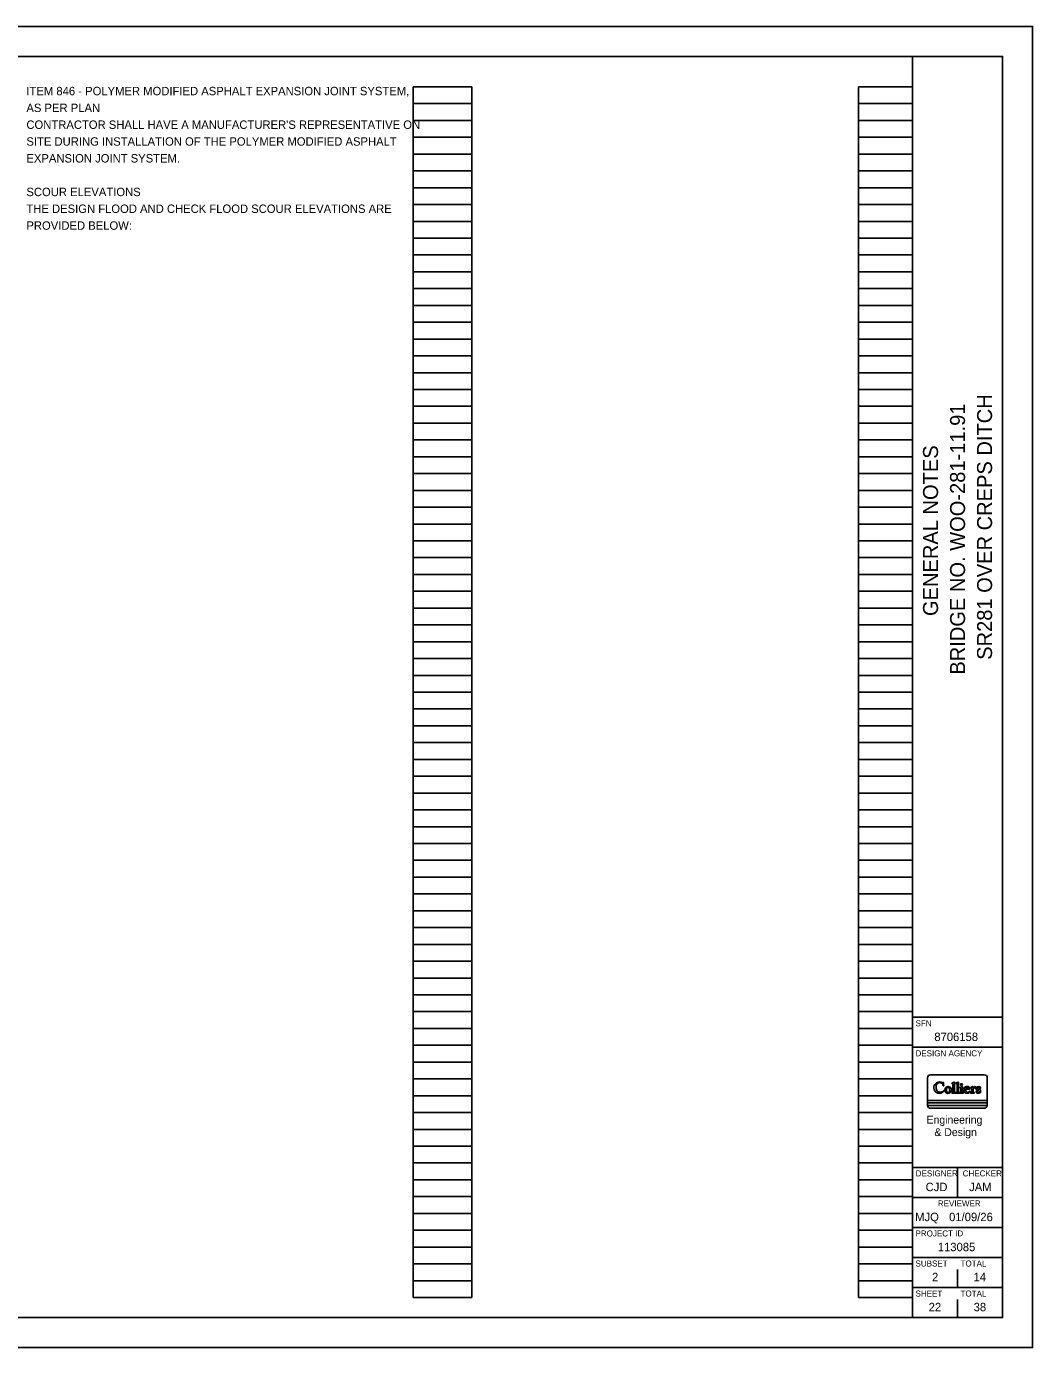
# Model space of a CAD drawing. Extents: x 0 to 34, y -0.1 to 22.
# Drawn here: x 17.24 to 34, y 0 to 22 of the extents above; entities that cross this region are included whole.
import ezdxf

# ---------------------------------------------------------------- set-up
doc = ezdxf.new("R2010")
doc.units = 0
for name, color, linetype in [('Default', 7, 'Continuous'), ('SH_Border', 7, 'Continuous'), ('SH_Cut_Line', 7, 'Continuous'), ('SH_Data', 7, 'Continuous'), ('SH_Text', 7, 'Continuous')]:
    doc.layers.add(name, color=color, linetype=linetype)

msp = doc.modelspace()

# ---------------------------------------------------------------- linework, layer by layer
at = {"layer": 'Default'}
for p, q in [((33.195, 4.543), (32.299, 4.543)), ((32.506, 4.413), (32.507, 4.41)), ((32.701, 4.252), (32.701, 4.416)), ((32.768, 4.251), (32.768, 4.416)), ((32.511, 4.364), (32.513, 4.359)), ((32.518, 4.265), (32.522, 4.27)), ((32.596, 4.346), (32.59, 4.346)), ((32.667, 4.245), (32.658, 4.245)), ((32.658, 4.237), (32.845, 4.237)), ((32.674, 4.381), (32.674, 4.253)), ((32.734, 4.245), (32.707, 4.245)), ((32.741, 4.379), (32.741, 4.251)), ((32.799, 4.245), (32.774, 4.245)), ((32.827, 4.346), (32.791, 4.332)), ((32.805, 4.312), (32.805, 4.251)), ((32.832, 4.249), (32.832, 4.343)), ((32.845, 4.245), (32.836, 4.245)), ((32.886, 4.302), (32.947, 4.302)), ((32.919, 4.31), (32.888, 4.31)), ((32.975, 4.245), (32.968, 4.245)), ((32.968, 4.237), (33.026, 4.237)), ((33, 4.346), (32.969, 4.331)), ((32.969, 4.325), (32.976, 4.321)), ((32.982, 4.31), (32.982, 4.253)), ((33.007, 4.328), (33.006, 4.343)), ((33.01, 4.253), (33.01, 4.307)), ((33.026, 4.245), (33.017, 4.245)), ((33.11, 4.333), (33.125, 4.316)), ((33.132, 4.32), (33.13, 4.335)), ((32.249, 4.033), (33.244, 4.033)), ((33.244, 4.033), (32.249, 4.033)), ((32.299, 3.986), (33.195, 3.986)), ((33.245, 4.035), (33.245, 4.075))]:
    msp.add_line(p, q, dxfattribs=at)
for points in [[(32.249, 4.493), (32.249, 4.117), (33.245, 4.117), (33.245, 4.493)], [(32.521, 4.361), (32.516, 4.386), (32.514, 4.414)], [(33.245, 4.075), (32.249, 4.075), (32.249, 4.035)]]:
    msp.add_lwpolyline(points, dxfattribs=at)
msp.add_lwpolyline([(33.245, 4.117), (32.249, 4.117), (32.249, 4.075), (33.245, 4.075)], close=True, dxfattribs=at)
msp.add_circle((32.815, 4.379), 0.0155, dxfattribs=at)
for centre, radius, start, end in [((32.299, 4.493), 0.0498, 90, 180), ((32.456, 4.326), 0.0996, 122.7772, 219.4331), ((32.457, 4.348), 0.0652, 110.6135, 175.9543), ((32.45, 4.335), 0.0884, 54.7696, 122.7772), ((32.45, 4.367), 0.0454, 67.8997, 110.6135), ((32.437, 4.335), 0.0794, 21.2674, 67.8997), ((32.503, 4.41), 0.00381, 234.7696, 0.2433), ((32.51, 4.414), 0.00392, 10.93, 183.8175), ((32.657, 4.401), 0.00323, 122.5943, 271.3615), ((32.544, 4.721), 0.336, 289.2258, 296.5694), ((32.696, 4.416), 0.00466, 0.7043, 112.8976), ((32.724, 4.402), 0.00377, 108.5217, 257.147), ((32.641, 4.668), 0.275, 287.2899, 295.7863), ((32.763, 4.416), 0.00504, 3.9002, 114.2106), ((33.195, 4.493), 0.0498, 0, 90), ((32.445, 4.317), 0.0857, 219.4331, 285.3506), ((32.526, 4.343), 0.135, 175.9543, 206.5569), ((32.458, 4.31), 0.059, 206.5569, 271.2175), ((32.458, 4.328), 0.0773, 271.2175, 317.7042), ((32.44, 4.334), 0.104, 285.3506, 318.3029), ((32.516, 4.362), 0.00427, 213.048, 354.7379), ((32.518, 4.273), 0.00456, 317.5815, 137.7042), ((32.594, 4.29), 0.0573, 155.0154, 195.9836), ((32.593, 4.29), 0.0568, 195.9836, 247.4134), ((32.591, 4.291), 0.0549, 91.4708, 155.0154), ((32.627, 4.29), 0.0628, 159.8672, 197.1421), ((32.617, 4.287), 0.0527, 197.1421, 229.9048), ((32.613, 4.295), 0.0485, 128.4847, 159.8672), ((32.591, 4.284), 0.0512, 247.4134, 292.5866), ((32.592, 4.322), 0.0143, 51.5153, 128.4847), ((32.593, 4.259), 0.0157, 229.9048, 310.0952), ((32.596, 4.291), 0.0547, 22.5432, 90), ((32.572, 4.297), 0.0457, 8.6045, 51.5153), ((32.573, 4.282), 0.0463, 311.5123, 356.3189), ((32.586, 4.297), 0.0652, 292.5866, 340.2533), ((32.532, 4.287), 0.0872, 354.2931, 11.1311), ((32.599, 4.292), 0.0508, 340.2533, 22.5432), ((32.658, 4.241), 0.00412, 90, 270), ((32.657, 4.381), 0.0166, 0, 91.3615), ((32.667, 4.252), 0.00695, 270, 7.6881), ((32.709, 4.252), 0.00806, 180, 256.9766), ((32.722, 4.379), 0.019, 0, 85.065), ((32.734, 4.251), 0.0065, 270, 3.1556), ((32.775, 4.251), 0.00652, 179.2506, 264.6402), ((32.794, 4.329), 0.00399, 126.9098, 263.7558), ((32.792, 4.312), 0.0128, 0, 83.7558), ((32.799, 4.25), 0.00532, 270, 12.3402), ((32.829, 4.343), 0.00324, 356.2318, 111.3032), ((32.837, 4.249), 0.00485, 180, 266.7746), ((32.845, 4.241), 0.00381, 270, 90), ((32.936, 4.289), 0.0786, 158.9201, 196.7689), ((32.904, 4.28), 0.0455, 196.7689, 259.4625), ((32.906, 4.301), 0.0468, 107.3884, 158.9201), ((32.928, 4.294), 0.0459, 174.8749, 230.9242), ((32.886, 4.298), 0.00367, 90, 174.8749), ((32.917, 4.307), 0.0332, 120.4846, 167.2691), ((32.888, 4.313), 0.00338, 167.2691, 270), ((32.909, 4.292), 0.0557, 72.6116, 107.3884), ((32.906, 4.29), 0.0563, 259.4625, 329.9587), ((32.92, 4.284), 0.0321, 230.9242, 328.1623), ((32.907, 4.323), 0.0144, 42.3189, 120.4846), ((32.901, 4.317), 0.0231, 354.1231, 42.3189), ((32.918, 4.315), 0.00543, 277.2594, 354.1231), ((32.914, 4.309), 0.0381, 357.2625, 72.6116), ((32.946, 4.307), 0.00555, 272.7564, 357.2625), ((32.951, 4.264), 0.00454, 329.9587, 148.1623), ((32.968, 4.241), 0.00381, 91.0116, 270), ((32.971, 4.328), 0.0034, 121.2415, 241.2505), ((32.975, 4.252), 0.00704, 270, 9.7141), ((32.969, 4.31), 0.0136, 0, 59.7444), ((33.002, 4.343), 0.00375, 6.4513, 116.174), ((33.009, 4.328), 0.00158, 185.3907, 323.4477), ((33.094, 4.265), 0.104, 130.2856, 143.4477), ((33.033, 4.307), 0.0235, 141.4263, 180.0327), ((33.018, 4.252), 0.00796, 179.3196, 263.9925), ((33.023, 4.315), 0.0105, 58.8554, 141.4263), ((33.038, 4.331), 0.0179, 49.7144, 130.2856), ((33.026, 4.241), 0.00381, 270, 90), ((33.038, 4.339), 0.018, 238.8554, 310.2856), ((33.041, 4.335), 0.0124, 310.2856, 49.7144), ((33.093, 4.312), 0.0332, 143.4089, 199.3264), ((33.065, 4.268), 0.00485, 20.4198, 193.2731), ((32.948, 4.24), 0.116, 4.8826, 13.2731), ((33.087, 4.31), 0.0263, 199.3264, 242.7351), ((33.077, 4.251), 0.014, 184.8826, 242.2064), ((33.093, 4.312), 0.0334, 105.6066, 143.4089), ((33.118, 4.287), 0.0516, 200.4198, 231.7135), ((33.093, 4.282), 0.0486, 242.2064, 319.0024), ((33.141, 4.415), 0.144, 242.7351, 255.1442), ((33.093, 4.322), 0.0133, 123.6114, 236.3886), ((33.099, 4.29), 0.0558, 61.5074, 105.6066), ((33.099, 4.313), 0.0238, 78.1441, 123.6114), ((33.111, 4.35), 0.0468, 236.3886, 262.0524), ((33.098, 4.261), 0.0185, 231.7135, 325.4966), ((33.101, 4.325), 0.0115, 42.5173, 78.1441), ((33.1, 4.26), 0.016, 325.4966, 75.1442), ((33.099, 4.263), 0.0407, 40.9976, 82.0524), ((33.128, 4.319), 0.00433, 219.7222, 9.1323), ((33.122, 4.333), 0.00795, 16.8946, 61.5074), ((33.107, 4.27), 0.0305, 319.0024, 40.9976), ((32.299, 4.035), 0.0498, 180, 183.1495), ((32.299, 4.035), 0.0498, 183.1495, 270), ((33.195, 4.035), 0.0498, 270, 356.8505), ((33.195, 4.035), 0.0498, 356.8505, 0)]:
    msp.add_arc(centre, radius, start, end, dxfattribs=at)
at = {"layer": 'SH_Border'}
for p, q in [((32, 0.5), (32, 21.5)), ((32, 5.5), (33.5, 5.5)), ((32, 5), (33.5, 5)), ((32, 3), (33.5, 3)), ((32.75, 3), (32.75, 2.5)), ((32, 2.5), (33.5, 2.5)), ((32, 2), (33.5, 2)), ((32, 1.5), (33.5, 1.5)), ((32, 1), (33.5, 1))]:
    msp.add_line(p, q, dxfattribs=at)
msp.add_lwpolyline([(1.5, 21.5), (33.5, 21.5), (33.5, 0.5), (1.5, 0.5)], close=True, dxfattribs=at)
at = {"layer": 'SH_Cut_Line'}
msp.add_lwpolyline([(0, 0), (34, 0), (34, 22), (0, 22)], close=True, dxfattribs=at)
at = {"layer": 'SH_Data'}
for p, q in [((23.68, 0.834), (23.68, 20.994)), ((23.68, 20.994), (24.66, 20.994)), ((24.66, 0.834), (24.66, 20.994)), ((31.1, 0.834), (31.1, 20.994)), ((31.1, 20.994), (32, 20.994)), ((32, 0.834), (32, 20.994)), ((23.68, 20.714), (24.66, 20.714)), ((31.1, 20.714), (32, 20.714)), ((23.68, 20.434), (24.66, 20.434)), ((31.1, 20.434), (32, 20.434)), ((23.68, 20.154), (24.66, 20.154)), ((31.1, 20.154), (32, 20.154)), ((23.68, 19.874), (24.66, 19.874)), ((31.1, 19.874), (32, 19.874)), ((23.68, 19.594), (24.66, 19.594)), ((31.1, 19.594), (32, 19.594)), ((23.68, 19.314), (24.66, 19.314)), ((31.1, 19.314), (32, 19.314)), ((23.68, 19.034), (24.66, 19.034)), ((31.1, 19.034), (32, 19.034)), ((23.68, 18.754), (24.66, 18.754)), ((31.1, 18.754), (32, 18.754)), ((23.68, 18.474), (24.66, 18.474)), ((31.1, 18.474), (32, 18.474)), ((23.68, 18.194), (24.66, 18.194)), ((31.1, 18.194), (32, 18.194)), ((23.68, 17.914), (24.66, 17.914)), ((31.1, 17.914), (32, 17.914)), ((23.68, 17.634), (24.66, 17.634)), ((31.1, 17.634), (32, 17.634)), ((23.68, 17.354), (24.66, 17.354)), ((31.1, 17.354), (32, 17.354)), ((23.68, 17.074), (24.66, 17.074)), ((31.1, 17.074), (32, 17.074)), ((23.68, 16.794), (24.66, 16.794)), ((31.1, 16.794), (32, 16.794)), ((23.68, 16.514), (24.66, 16.514)), ((31.1, 16.514), (32, 16.514)), ((23.68, 16.234), (24.66, 16.234)), ((31.1, 16.234), (32, 16.234)), ((23.68, 15.954), (24.66, 15.954)), ((31.1, 15.954), (32, 15.954)), ((23.68, 15.674), (24.66, 15.674)), ((31.1, 15.674), (32, 15.674)), ((23.68, 15.394), (24.66, 15.394)), ((31.1, 15.394), (32, 15.394)), ((23.68, 15.114), (24.66, 15.114)), ((31.1, 15.114), (32, 15.114)), ((23.68, 14.834), (24.66, 14.834)), ((31.1, 14.834), (32, 14.834)), ((23.68, 14.554), (24.66, 14.554)), ((31.1, 14.554), (32, 14.554)), ((23.68, 14.274), (24.66, 14.274)), ((31.1, 14.274), (32, 14.274)), ((23.68, 13.994), (24.66, 13.994)), ((31.1, 13.994), (32, 13.994)), ((23.68, 13.714), (24.66, 13.714)), ((31.1, 13.714), (32, 13.714)), ((23.68, 13.434), (24.66, 13.434)), ((31.1, 13.434), (32, 13.434)), ((23.68, 13.154), (24.66, 13.154)), ((31.1, 13.154), (32, 13.154)), ((23.68, 12.874), (24.66, 12.874)), ((31.1, 12.874), (32, 12.874)), ((23.68, 12.594), (24.66, 12.594)), ((31.1, 12.594), (32, 12.594)), ((23.68, 12.314), (24.66, 12.314)), ((31.1, 12.314), (32, 12.314)), ((23.68, 12.034), (24.66, 12.034)), ((31.1, 12.034), (32, 12.034)), ((23.68, 11.754), (24.66, 11.754)), ((31.1, 11.754), (32, 11.754)), ((23.68, 11.474), (24.66, 11.474)), ((31.1, 11.474), (32, 11.474)), ((23.68, 11.194), (24.66, 11.194)), ((31.1, 11.194), (32, 11.194)), ((23.68, 10.914), (24.66, 10.914)), ((31.1, 10.914), (32, 10.914)), ((23.68, 10.634), (24.66, 10.634)), ((31.1, 10.634), (32, 10.634)), ((23.68, 10.354), (24.66, 10.354)), ((31.1, 10.354), (32, 10.354)), ((23.68, 10.074), (24.66, 10.074)), ((31.1, 10.074), (32, 10.074)), ((23.68, 9.794), (24.66, 9.794)), ((31.1, 9.794), (32, 9.794)), ((23.68, 9.514), (24.66, 9.514)), ((31.1, 9.514), (32, 9.514)), ((23.68, 9.234), (24.66, 9.234)), ((31.1, 9.234), (32, 9.234)), ((23.68, 8.954), (24.66, 8.954)), ((31.1, 8.954), (32, 8.954)), ((23.68, 8.674), (24.66, 8.674)), ((31.1, 8.674), (32, 8.674)), ((23.68, 8.394), (24.66, 8.394)), ((31.1, 8.394), (32, 8.394)), ((23.68, 8.114), (24.66, 8.114)), ((31.1, 8.114), (32, 8.114)), ((23.68, 7.834), (24.66, 7.834)), ((31.1, 7.834), (32, 7.834)), ((23.68, 7.554), (24.66, 7.554)), ((31.1, 7.554), (32, 7.554)), ((23.68, 7.274), (24.66, 7.274)), ((31.1, 7.274), (32, 7.274)), ((23.68, 6.994), (24.66, 6.994)), ((31.1, 6.994), (32, 6.994)), ((23.68, 6.714), (24.66, 6.714)), ((31.1, 6.714), (32, 6.714)), ((23.68, 6.434), (24.66, 6.434)), ((31.1, 6.434), (32, 6.434)), ((23.68, 6.154), (24.66, 6.154)), ((31.1, 6.154), (32, 6.154)), ((23.68, 5.874), (24.66, 5.874)), ((31.1, 5.874), (32, 5.874)), ((23.68, 5.594), (24.66, 5.594)), ((31.1, 5.594), (32, 5.594)), ((23.68, 5.314), (24.66, 5.314)), ((31.1, 5.314), (32, 5.314)), ((23.68, 5.034), (24.66, 5.034)), ((31.1, 5.034), (32, 5.034)), ((23.68, 4.754), (24.66, 4.754)), ((31.1, 4.754), (32, 4.754)), ((23.68, 4.474), (24.66, 4.474)), ((31.1, 4.474), (32, 4.474)), ((23.68, 4.194), (24.66, 4.194)), ((31.1, 4.194), (32, 4.194)), ((32.75, 4), (32.75, 4)), ((23.68, 3.914), (24.66, 3.914)), ((31.1, 3.914), (32, 3.914)), ((23.68, 3.634), (24.66, 3.634)), ((31.1, 3.634), (32, 3.634)), ((23.68, 3.354), (24.66, 3.354)), ((31.1, 3.354), (32, 3.354)), ((23.68, 3.074), (24.66, 3.074)), ((31.1, 3.074), (32, 3.074)), ((23.68, 2.794), (24.66, 2.794)), ((31.1, 2.794), (32, 2.794)), ((23.68, 2.514), (24.66, 2.514)), ((31.1, 2.514), (32, 2.514)), ((23.68, 2.234), (24.66, 2.234)), ((31.1, 2.234), (32, 2.234)), ((23.68, 1.954), (24.66, 1.954)), ((31.1, 1.954), (32, 1.954)), ((23.68, 1.674), (24.66, 1.674)), ((31.1, 1.674), (32, 1.674)), ((23.68, 1.394), (24.66, 1.394)), ((31.1, 1.394), (32, 1.394)), ((23.68, 1.114), (24.66, 1.114)), ((31.1, 1.114), (32, 1.114)), ((32.75, 1), (32.75, 1.3)), ((23.68, 0.834), (24.66, 0.834)), ((31.1, 0.834), (32, 0.834)), ((32.375, 0.675), (32.375, 0.675)), ((32.75, 0.5), (32.75, 0.8))]:
    msp.add_line(p, q, dxfattribs=at)

# ---------------------------------------------------------------- texts
at = {"layer": 'Default'}
for s, height, p in [('Engineering', 0.13025, (32.234, 3.729)), ('& Design', 0.1303, (32.365, 3.522))]:
    msp.add_text(s, height=height, dxfattribs=at).set_placement(p)
at = {"layer": 'SH_Data'}
for s, p in [('SR281 OVER CREPS DITCH', (33.325, 11.453)), ('BRIDGE NO. WOO-281-11.91', (32.875, 11.206)), ('GENERAL NOTES', (32.425, 12.182))]:
    msp.add_text(s, height=0.25, rotation=90, dxfattribs=at).set_placement(p)
for s, height, p in [('SFN', 0.1, (32.05, 5.35)), ('8706158', 0.14, (32.363, 5.105)), ('DESIGN AGENCY', 0.1, (32.05, 4.85)), ('DESIGNER', 0.1, (32.054, 2.85)), ('CHECKER', 0.1, (32.835, 2.85)), ('CJD', 0.14, (32.218, 2.605)), ('JAM', 0.14, (32.943, 2.605)), ('REVIEWER', 0.1, (32.422, 2.35)), ('MJQ', 0.14, (32.044, 2.105)), ('01/09/26', 0.14, (32.609, 2.105)), ('PROJECT ID', 0.1, (32.05, 1.85)), ('113085', 0.14, (32.421, 1.605)), ('SUBSET', 0.1, (32.05, 1.35)), ('TOTAL', 0.1, (32.8, 1.35)), ('2', 0.14, (32.325, 1.105)), ('14', 0.14, (33.016, 1.105)), ('SHEET', 0.1, (32.05, 0.85)), ('TOTAL', 0.1, (32.8, 0.85)), ('22', 0.14, (32.269, 0.605)), ('38', 0.14, (33.018, 0.605))]:
    msp.add_text(s, height=height, dxfattribs=at).set_placement(p)
at = {"layer": 'SH_Text'}
for s, p in [('ITEM 846 - POLYMER MODIFIED ASPHALT EXPANSION JOINT SYSTEM, ', (17.24, 20.854)), ('AS PER PLAN', (17.24, 20.574)), ("CONTRACTOR SHALL HAVE A MANUFACTURER'S REPRESENTATIVE ON ", (17.24, 20.294)), ('SITE DURING INSTALLATION OF THE POLYMER MODIFIED ASPHALT ', (17.24, 20.014)), ('EXPANSION JOINT SYSTEM.', (17.24, 19.734)), ('SCOUR ELEVATIONS', (17.24, 19.174)), ('THE DESIGN FLOOD AND CHECK FLOOD SCOUR ELEVATIONS ARE ', (17.24, 18.894)), ('PROVIDED BELOW:', (17.24, 18.614))]:
    msp.add_text(s, height=0.14, dxfattribs=at).set_placement(p)

doc.saveas('drawing.dxf')
